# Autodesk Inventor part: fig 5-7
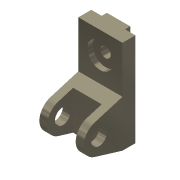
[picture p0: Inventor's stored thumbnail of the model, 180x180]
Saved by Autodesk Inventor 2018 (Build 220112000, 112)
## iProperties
Shininess: 65.0
Angle Display Precision: 2
Document Length Units: 11269
Document Angle Units: 11279
Document Time Units: 11290
Document Mass Units: 11283
Document Length Units Precision: 3
Document Angle Units Precision: 2
Compacted: False
Created: 2001-11
Part Number: fig 5-7
Document SubType Name: Modeling
Designer: Renu Muthoo
Density: 1 g/cm^3
Material: Generic
Appearance: Metal-Titanium (Polished)
Density: 0.0
Volumn: 0.0
Area: 0.0
PropertySet Name: Model Information
Control State: 0
Master: False
Checked Out: False
Author: Renu Muthoo
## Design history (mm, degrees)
node "Sketch1"
sketch "Sketch2"
  geometry: L1 (33.257, 104.664)-(33.257, -75.336); L2 (33.257, -75.336)-(8.257, -75.336); L3 (8.257, -75.336)-(-45.451, -59.045); L4 (-45.451, -1.628)-(8.257, 14.664); L5 (8.257, 14.664)-(8.257, 104.664); L6 (8.257, 104.664)-(33.257, 104.664); C1 r 15 at (-36.743, -30.336); A1 r 30 centre (-36.743, -30.336) between (-45.451, -1.628) and (-45.451, -59.045)
  constraints: 12 end point, 2 centre point, 2 equal length, 2 parallel, 2 point on circle, 2 tangent, 1 coincident, 1 perpendicular, 1 vertical
  dimensions: "d0" = 180 distance of L1.start L1.end; "d1" = 30 radius of A1; "d2" = 25 distance of L5.end L1.start; "d3" = 45 distance from line of L2 A1.centre; "d4" = 70 distance from line of L1 A1.centre; "d5" = 30 diameter of C1
extrude "Extrusion1" new body sketch "Sketch2" distance "d6" = 85; taper "d7" = 0 deg
workplane "Work Plane1"
sketch "Sketch3"
  geometry: L1 (15, 62.364)-(70, 62.364); L2 (70, 62.364)-(70, -52.386); L3 (70, -52.386)-(15, -52.386); L4 (15, -52.386)-(15, 62.364); L5 (0, -45)-(0, -28.708) reference
  constraints: 8 end point, 2 parallel, 1 horizontal, 1 perpendicular
  dimensions: "d8" = 55 distance of L1.start L1.end; "d9" = 15 distance between parallel lines of L5 L4
extrude "Extrusion2" cut sketch "Sketch3" distance "d10" = 50; taper "d11" = 0 deg
sketch "Sketch4"
  geometry: L1 (0, 25)-(85, 25) reference; L2 (0, 0)-(0, 25) reference; L3 (20, 25)-(65, 25); L4 (65, 25)-(65, 35); L5 (65, 35)-(20, 35); L6 (20, 35)-(20, 25)
  constraints: 8 end point, 2 parallel, 1 horizontal, 1 perpendicular, 1 point on line
  dimensions: "d12" = 45 distance of L4.end L5.end; "d13" = 10 distance of L3.end L4.end; "d14" = 20 distance between parallel lines of L2 L6
extrude "Extrusion3" join sketch "Sketch4" stored distance "d15" = 50; taper "d16" = 0 deg
sketch "Sketch5"
  geometry: L1 (85, 0)-(85, 90) reference; L2 (0, 90)-(85, 90) reference; 1 further point
  dimensions: "d17" = 42 distance from line of L2 point (42.5, 48); "d18" = 42.5 distance from line of L1 point (42.5, 48)
hole "Hole1" sketch "Sketch5" at (42.5, 48) diameter "d19" = 20; stored, may be unused: countersink angle "d23" = 82 deg, drill point angle "d25" = 118 deg; dims "d20" = 6, "d21" = 50, "d22" = 10, "d24" = 8
body "Solid1"
